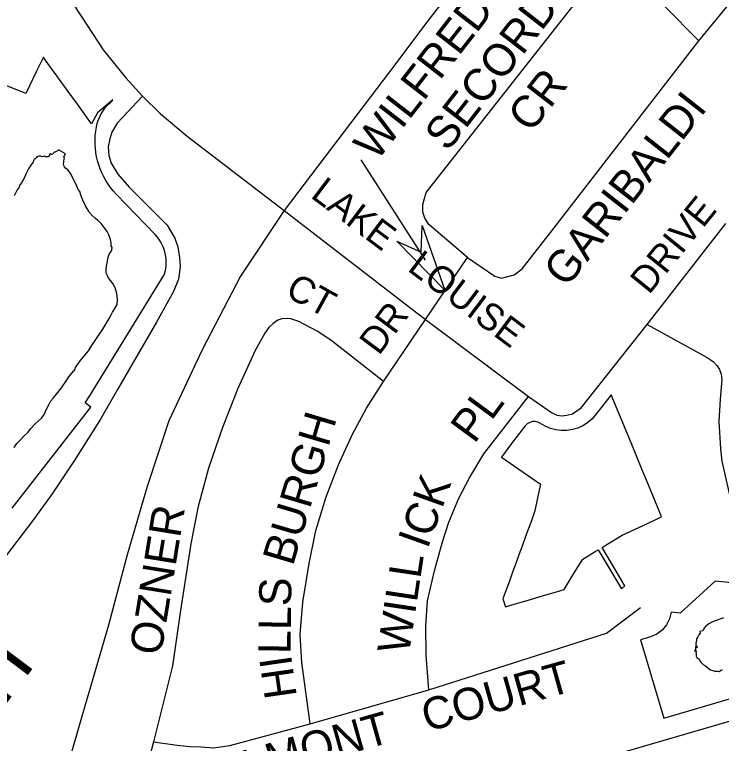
# Model space of a CAD drawing. Extents: x 586326 to 623965, y 4819854 to 4857850.
# Drawn here: x 595356 to 595831.2, y 4836716.7 to 4837206.8 of the extents above; entities that cross this region are included whole.
import ezdxf

# ---------------------------------------------------------------- set-up
doc = ezdxf.new("R2010")
doc.units = 0
for name, color, linetype in [('Major Rds and Hwys', 7, 'Continuous'), ('Minor Rd Lbls', 7, 'Continuous'), ('Minor Rds', 7, 'Continuous'), ('Park Outlines', 7, 'Continuous'), ('Proposed Secondary Rds', 7, 'Continuous'), ('Pts of Interest', 7, 'Continuous'), ('Railways_lbls', 7, 'Continuous'), ('SWM Ponds', 7, 'Continuous')]:
    doc.layers.add(name, color=color, linetype=linetype)

msp = doc.modelspace()

# ---------------------------------------------------------------- linework, layer by layer
at = {"layer": 'Major Rds and Hwys'}
for points in [[(595760.45, 4837366.75), (595633.22, 4837201.64), (595608.03, 4837168.25), (595591.04, 4837145.83), (595537.32, 4837074.96)], [(595537.32, 4837074.96), (595508.03, 4837030.94), (595482.16, 4836981.47), (595459.78, 4836933.73), (595445.14, 4836889.38), (595431.71, 4836843.47), (595419.12, 4836796.3), (595400.24, 4836730.99), (595381.15, 4836664.64), (595369.81, 4836634.99), (595354.27, 4836602.03), (595344.33, 4836583.96)]]:
    msp.add_lwpolyline(points, dxfattribs=at)
at = {"layer": 'Minor Rd Lbls'}
for p, q in [((595632.33, 4837041.62), (595588.99, 4837109.18)), ((595629.39, 4837046.93), (595629.97, 4837064.94)), ((595629.97, 4837064.94), (595645.22, 4837021.44)), ((595645.22, 4837021.44), (595612.98, 4837054.39)), ((595612.98, 4837054.39), (595629.39, 4837046.93)), ((595629.39, 4837046.93), (595629.39, 4837046.93))]:
    msp.add_line(p, q, dxfattribs=at)
msp.add_lwpolyline([(595629.39, 4837046.93), (595629.97, 4837064.94), (595645.22, 4837021.44), (595612.98, 4837054.39)], close=True, dxfattribs=at)
at = {"layer": 'Minor Rds'}
for points in [[(595816.09, 4837189.21), (595870.42, 4837255.45)], [(595660.62, 4837043.45), (595634.47, 4837065.73), (595631.93, 4837069.91), (595630.48, 4837074.01), (595630.52, 4837079.01), (595632.85, 4837087.11), (595741.37, 4837225.39), (595746.45, 4837231.88), (595751.37, 4837236.4), (595756.71, 4837239.21), (595761.94, 4837239.65), (595766.28, 4837238.26), (595769.87, 4837235.91), (595816.09, 4837189.21)], [(595660.62, 4837043.45), (595678.94, 4837030.95), (595683.45, 4837029.62), (595691.82, 4837031.78), (595697.2, 4837035.87), (595718.77, 4837063.47), (595816.09, 4837189.21)], [(595442.14, 4837151.85), (595424.96, 4837133.76), (595421.31, 4837127.7), (595419.98, 4837123.27), (595418.99, 4837117.77), (595419.46, 4837111.97), (595420.94, 4837106.91), (595425.38, 4837099.52), (595433.16, 4837090.84), (595458.52, 4837065.15), (595463.73, 4837056.52), (595465.81, 4837050.55), (595466.98, 4837043.49), (595467.46, 4837037.08), (595466.27, 4837028.88), (595462.78, 4837020.52), (595451.52, 4836999.98), (595425.34, 4836954.79), (595413.77, 4836934.7), (595396.18, 4836906.81), (595381.36, 4836884.59), (595368.33, 4836866.52), (595219.78, 4836671.9), (595190.87, 4836634.67)], [(595537.32, 4837074.96), (595632.23, 4837001.85)], [(595781.42, 4836998.45), (595834.29, 4837066.24)], [(595632.23, 4837001.85), (595660.62, 4837043.45)], [(595604.16, 4836960.11), (595568.64, 4836987.78), (595559.57, 4836994.03), (595547.08, 4837000.42), (595541.79, 4837002.3), (595536.45, 4837002.4), (595533.1, 4837001.24), (595529.87, 4836999.1), (595526.95, 4836996.49), (595524.17, 4836992.66), (595517.88, 4836980.91), (595506.07, 4836955.26), (595495.82, 4836929.05), (595486.46, 4836901.7), (595479.26, 4836875.1), (595474.58, 4836850.94), (595467.5, 4836806.19), (595462.15, 4836768.78), (595449.37, 4836717.85)], [(595604.16, 4836960.11), (595632.23, 4837001.85)], [(595632.23, 4837001.85), (595701.63, 4836950.09)], [(595701.63, 4836950.09), (595716.98, 4836939.17), (595720.54, 4836937.47), (595724.07, 4836937.1), (595727.39, 4836937.37), (595731.08, 4836938.43), (595736.9, 4836942.36), (595781.42, 4836998.45)], [(595781.42, 4836998.45), (595821.58, 4836976.23), (595825.8, 4836973.46), (595828.22, 4836970.77), (595829.88, 4836968.04), (595830.96, 4836965.07), (595831.54, 4836961.31), (595830.29, 4836948.13), (595829.43, 4836933.25), (595830.61, 4836914.86), (595831.42, 4836906.5), (595837.77, 4836878.91), (595839.68, 4836874.12), (595841.55, 4836871.06), (595843.81, 4836868.23), (595847.06, 4836866.12), (595850.97, 4836864.45), (595855.91, 4836863.68), (595861.12, 4836864.08), (595920.01, 4836882.07)], [(595554.67, 4836729.81), (595549.24, 4836771.13), (595548.14, 4836790.05), (595549.84, 4836811.66), (595554.09, 4836837.81), (595558.63, 4836859.81), (595565.55, 4836882.58), (595573.7, 4836904.15), (595583.3, 4836924.7), (595592.68, 4836942.21), (595604.16, 4836960.11)], [(595634.59, 4836752.64), (595632.77, 4836776.16), (595632.51, 4836795.89), (595633.74, 4836812.5), (595638.44, 4836832.68), (595643.73, 4836852.3), (595647.95, 4836865.48), (595654.81, 4836881.61), (595661.92, 4836895.28), (595671.6, 4836911.35), (595701.63, 4836950.09)], [(595634.59, 4836752.64), (595754.01, 4836790.92), (595776.94, 4836808.09)], [(595554.67, 4836729.81), (595634.59, 4836752.64)], [(595449.37, 4836717.85), (595465.28, 4836715.61), (595473.79, 4836714.59), (595481.55, 4836714.42), (595489.68, 4836713.69), (595500.73, 4836715.31), (595554.67, 4836729.81)], [(595449.37, 4836717.85), (595440.59, 4836684.68), (595444.12, 4836667.28)]]:
    msp.add_lwpolyline(points, dxfattribs=at)
at = {"layer": 'Park Outlines'}
for points in [[(595354.32, 4836874.97), (595407.24, 4836942.84), (595403.6, 4836945.72), (595406.82, 4836950.9), (595456.67, 4837031.8), (595457.24, 4837033.8), (595457.66, 4837035.83), (595457.92, 4837037.89), (595458.01, 4837039.97), (595457.95, 4837042.04), (595457.73, 4837044.11), (595457.35, 4837046.15), (595456.82, 4837048.16), (595456.13, 4837050.11), (595455.29, 4837052.01), (595454.31, 4837053.85), (595453.2, 4837055.6), (595451.95, 4837057.25), (595450.58, 4837058.81), (595450.45, 4837058.94), (595424.58, 4837085.77), (595424.26, 4837086.11), (595422.35, 4837088.25), (595420.56, 4837090.49), (595418.89, 4837092.82), (595417.36, 4837095.25), (595415.97, 4837097.75), (595414.72, 4837100.33), (595413.61, 4837102.98), (595412.65, 4837105.68), (595411.85, 4837108.43), (595411.2, 4837111.23), (595410.7, 4837114.05), (595410.37, 4837116.9), (595410.19, 4837119.76), (595410.17, 4837122.63), (595410.32, 4837125.49), (595410.62, 4837128.34), (595411.08, 4837131.18), (595411.12, 4837131.38), (595411.62, 4837133.5), (595412.27, 4837135.57), (595413.08, 4837137.59), (595414.03, 4837139.54), (595415.13, 4837141.42), (595416.35, 4837143.22), (595417.71, 4837144.92), (595419.19, 4837146.51), (595420.78, 4837148), (595421.55, 4837148.77), (595422.12, 4837149.53), (595411.75, 4837140.82), (595407.85, 4837133.43), (595398.33, 4837146.54), (595391.41, 4837156.05), (595384.52, 4837165.54), (595376.68, 4837176.33), (595375.48, 4837178.18), (595370.88, 4837168.66), (595363.68, 4837153.78), (595339.46, 4837163.42)], [(595842.42, 4836824.18), (595826.97, 4836825.79), (595803.46, 4836804.32), (595797.42, 4836804.99), (595796.39, 4836800.55), (595794.36, 4836796.47), (595791.43, 4836792.97), (595787.77, 4836790.25), (595783.58, 4836788.45), (595776.85, 4836786.46), (595792.46, 4836733.65), (595995.06, 4836793.32)]]:
    msp.add_lwpolyline(points, dxfattribs=at)
msp.add_lwpolyline([(595685.98, 4836808.56), (595692.56, 4836810.51), (595699.13, 4836812.46), (595705.71, 4836814.4), (595712.28, 4836816.35), (595718.86, 4836818.3), (595725.44, 4836820.24), (595730.27, 4836828.09), (595733.41, 4836833.19), (595737.99, 4836840.63), (595739.88, 4836841.78), (595746.32, 4836845.69), (595746.72, 4836845.93), (595748.43, 4836846.97), (595764.1, 4836820.76), (595766.39, 4836822.77), (595750.99, 4836848.53), (595753.76, 4836850.21), (595754.97, 4836850.95), (595764.44, 4836856.7), (595778.57, 4836863.24), (595791.04, 4836869.02), (595790.23, 4836870.98), (595786.71, 4836879.51), (595781.97, 4836890.97), (595777.73, 4836901.24), (595773.39, 4836911.75), (595768.92, 4836922.58), (595757.12, 4836951.17), (595746.51, 4836937.56), (595744.01, 4836934.77), (595741.16, 4836932.36), (595738, 4836930.35), (595734.6, 4836928.8), (595731.01, 4836927.73), (595727.32, 4836927.16), (595723.58, 4836927.1), (595719.87, 4836927.55), (595716.25, 4836928.51), (595712.8, 4836929.95), (595709.58, 4836931.85), (595707.91, 4836932.72), (595706.07, 4836933.14), (595704.18, 4836933.09), (595702.37, 4836932.56), (595700.74, 4836931.61), (595699.41, 4836930.27), (595690.17, 4836918.36), (595683.44, 4836909.21), (595709.58, 4836890.99), (595707.7, 4836881.88), (595705.89, 4836873.07), (595703.69, 4836867.04), (595701.55, 4836861.16), (595699.41, 4836855.27), (595697.27, 4836849.41), (595695.14, 4836843.56), (595693.01, 4836837.71), (595690.87, 4836831.82), (595688.72, 4836825.93), (595686.55, 4836819.96), (595684.37, 4836813.99)], close=True, dxfattribs=at)
at = {"layer": 'Proposed Secondary Rds'}
for points in [[(595290.95, 4837327.72), (595358.01, 4837262.71), (595375.39, 4837243.38), (595380.84, 4837236.33), (595389.57, 4837222.98), (595401.35, 4837204.97), (595415.52, 4837183.05), (595423.17, 4837173.68), (595430.82, 4837164.31), (595442.14, 4837151.85)], [(595442.14, 4837151.85), (595453.83, 4837140.31), (595472.01, 4837125.01), (595537.32, 4837074.96)]]:
    msp.add_lwpolyline(points, dxfattribs=at)
at = {"layer": 'Railways_lbls'}
msp.add_lwpolyline([(595921.93, 4836756.32), (595564.93, 4836652.32), (595562.93, 4836651.32), (595017.93, 4836489.32)], dxfattribs=at)
at = {"layer": 'SWM Ponds'}
for points in [[(595355.3, 4836916.12), (595356.29, 4836915.95), (595356.41, 4836916.88), (595357.6, 4836918.28), (595359.83, 4836920.61), (595362.35, 4836923.31), (595365.16, 4836926), (595367.07, 4836928.57), (595369.68, 4836931.4), (595372.1, 4836933.58), (595374.15, 4836935.43), (595375.91, 4836937.82), (595377.34, 4836941.07), (595379.57, 4836945.23), (595380.42, 4836947.1), (595382.11, 4836949.13), (595384.27, 4836951.51), (595387.5, 4836955.9), (595391.01, 4836960.78), (595392.42, 4836963.23), (595396.69, 4836968.44), (595397.01, 4836969.5), (595400.22, 4836974), (595405.72, 4836980.78), (595408.4, 4836984.99), (595411.21, 4836989.1), (595415.41, 4836995.27), (595419.56, 4837002.39), (595420.95, 4837004.96), (595421.87, 4837006.78), (595422.86, 4837008.05), (595424.97, 4837011.79), (595425.13, 4837015.11), (595424.67, 4837019.34), (595423.7, 4837023.04), (595422.03, 4837025.97), (595420.46, 4837028.01), (595418.97, 4837029.99), (595418.18, 4837031.72), (595417.65, 4837033.25), (595417.52, 4837035.69), (595417.8, 4837037.61), (595418.35, 4837039.61), (595418.66, 4837042.73), (595419.66, 4837045.71), (595420.86, 4837047.51), (595421.35, 4837048.65), (595421.69, 4837050.12), (595421.02, 4837051.35), (595420.86, 4837053.1), (595420.43, 4837055.67), (595419.32, 4837058.67), (595418.25, 4837060.94), (595416.95, 4837062.66), (595415.59, 4837064.43), (595414.16, 4837066.37), (595412.08, 4837068.39), (595410.19, 4837069.87), (595408.21, 4837071.63), (595406.26, 4837073.96), (595405, 4837075.86), (595403.69, 4837078.2), (595401.92, 4837081.92), (595400.64, 4837085.36), (595399.83, 4837087.83), (595398.86, 4837089.19), (595397.95, 4837091.53), (595396.62, 4837094.39), (595395.31, 4837096.74), (595394.14, 4837099.28), (595392.74, 4837101.39), (595391.75, 4837102.47), (595390.25, 4837103.59), (595389.6, 4837104.4), (595389.2, 4837105.38), (595388.92, 4837106.46), (595389.04, 4837107.64), (595389.18, 4837108.5), (595389.31, 4837109.36), (595389.67, 4837109.94), (595389.47, 4837110.6), (595389.24, 4837111.34), (595389.64, 4837111.86), (595389.73, 4837112.43), (595390.23, 4837113.26), (595385.58, 4837115.77), (595384.63, 4837114.92), (595383.63, 4837114.51), (595382.99, 4837114.34), (595382.51, 4837113.86), (595381.64, 4837113.01), (595380.91, 4837112.72), (595380.21, 4837113.06), (595379.58, 4837112.9), (595379.53, 4837112.32), (595379.43, 4837111.79), (595378.56, 4837111.2), (595377.63, 4837111.12), (595376.82, 4837111.19), (595376.08, 4837111.67), (595375.37, 4837111.41), (595374.59, 4837111.2), (595373.64, 4837111.54), (595372.33, 4837111.55), (595371.05, 4837111.22), (595370.59, 4837110.37), (595369.91, 4837109.88), (595369.17, 4837109.34), (595368.82, 4837108.49), (595368.47, 4837107.65), (595367.38, 4837106.26), (595365.71, 4837103.61), (595364.7, 4837101.66), (595363.65, 4837099.53), (595362.38, 4837096.86), (595361.41, 4837094.98), (595360.86, 4837093.88), (595359.68, 4837092.37), (595359.08, 4837090.7), (595357.77, 4837088.88), (595356.62, 4837086.63), (595355.73, 4837084.98)], [(595832.53, 4836801.25), (595830.83, 4836800.54), (595828.36, 4836799.54), (595825.58, 4836798.6), (595822.82, 4836797.11), (595820.6, 4836795.3), (595819.27, 4836793.59), (595818.66, 4836792.47), (595816.72, 4836792.03), (595816.87, 4836790.75), (595816.1, 4836789.76), (595815.36, 4836788.47), (595814.59, 4836787.03), (595814.39, 4836786.21), (595814.24, 4836785), (595814.07, 4836783.98), (595814.13, 4836782.69), (595814.63, 4836782.08), (595814.8, 4836781.68), (595814.82, 4836781.08), (595814.35, 4836781.45), (595813.71, 4836781.82), (595813.91, 4836780.59), (595813.76, 4836779.83), (595813.25, 4836779.07), (595814.59, 4836779.08), (595814.14, 4836778.28), (595814.16, 4836776.94), (595814.16, 4836775.34), (595814.71, 4836774.46), (595816.19, 4836773.4), (595816.73, 4836772.27), (595817.3, 4836771.29), (595818.97, 4836769.8), (595820.59, 4836768.8), (595822.36, 4836767.43), (595823.9, 4836766.22), (595825.51, 4836765.67), (595826.6, 4836765.36), (595827.24, 4836765.38), (595828.89, 4836765.34), (595829.62, 4836765.13), (595830.65, 4836765.65), (595831.94, 4836766.51)]]:
    msp.add_lwpolyline(points, dxfattribs=at)

# ---------------------------------------------------------------- texts
at = {"layer": 'Minor Rd Lbls'}
for s, height, rotation, p in [('WILFRED GATE', 21.6, 52.1849, (595599.56, 4837107.56)), ('SECORD ', 21.6, 52.1849, (595647.21, 4837114.06)), ('CR', 21.6, 52.1849, (595703.18, 4837126.52)), ('GARIBALDI', 21.6, 51.8471, (595727.12, 4837022.52)), ('LAKE   LOUISE ', 18, 322.9424, (595554.33, 4837084.29)), ('DRIVE', 18, 51.003, (595782.55, 4837017.96)), ('CT', 18, 331.2129, (595537.22, 4837017.95)), ('DR', 18, 53.2379, (595600.97, 4836976.97)), ('PL', 21.6, 53.5682, (595665.08, 4836917.65)), ('BURGH', 21.6, 73.4358, (595543.1, 4836835.42)), ('ICK', 21.6, 70.2734, (595633.67, 4836846.85)), ('OZNER', 21.6, 80.7849, (595454.45, 4836775.22)), ('WILL', 21.6, 81.4851, (595621.2, 4836776.21)), ('LLS', 21.6, 89.1555, (595541.5, 4836776.71)), ('WILMONT   COURT', 21.6, 15.7199, (595478.81, 4836680.84)), ('HI', 21.6, 98.188, (595545.89, 4836748.42))]:
    msp.add_text(s, height=height, rotation=rotation, dxfattribs=at).set_placement(p)
at = {"layer": 'Pts of Interest'}
msp.add_text('PLEASANT', height=39.984, rotation=53.1768, dxfattribs=at).set_placement((595208.87, 4836554.21))

doc.saveas('drawing.dxf')
